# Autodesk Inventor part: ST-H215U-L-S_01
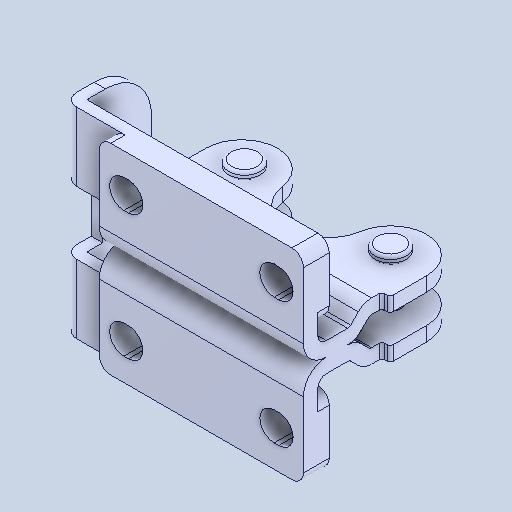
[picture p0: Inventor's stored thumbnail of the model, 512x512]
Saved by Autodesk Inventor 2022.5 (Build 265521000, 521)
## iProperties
Created: 2024-07
Part Number: ST-H215U-L-S_01
Material: 一般
Document SubType Name: Modeling
Designer: ImaoCorp
Density: 1 g/cm^3
Appearance: 既定
Author: ImaoCorp
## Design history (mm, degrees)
feature "ST-H215U-L-S_01"
node "ソリッド1"
